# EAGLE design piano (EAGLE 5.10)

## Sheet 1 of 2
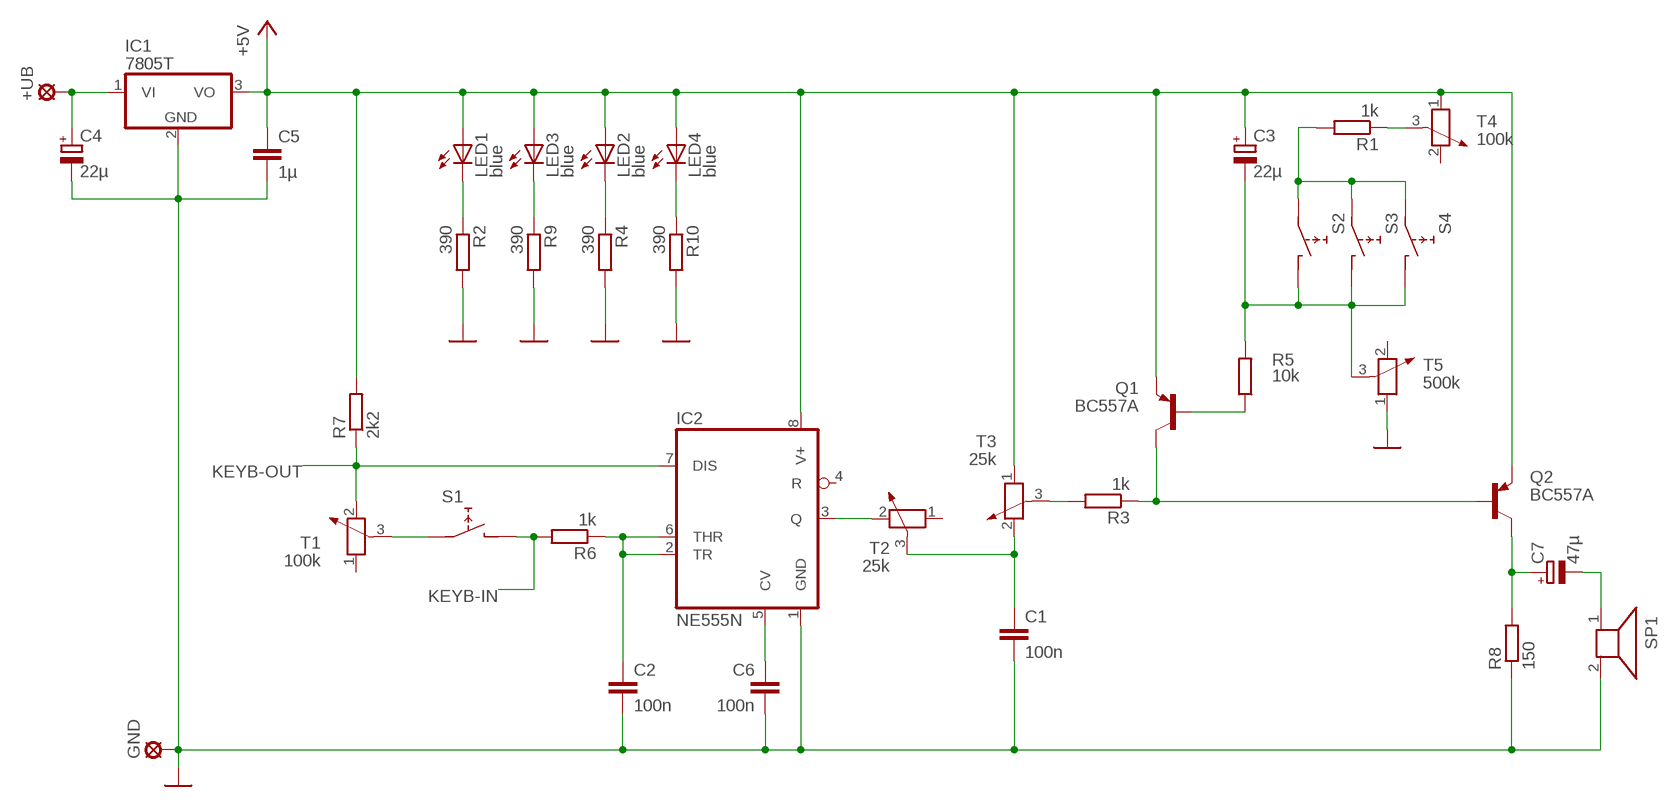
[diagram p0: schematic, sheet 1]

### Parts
+UB  LSP10  [LSP10]
C1  100n  C-EU075-063X106  [C075-063X106]
C2  100n  C-EU075-063X106  [C075-063X106]
C3  22µ  CPOL-EUB45181D  [B45181D]
C4  22µ  CPOL-EUB45181D  [B45181D]
C5  1µ  C-EU075-063X106  [C075-063X106]
C6  100n  C-EU075-063X106  [C075-063X106]
C7  47µ  CPOL-EUB45181D  [B45181D]
GND  LSP10  [LSP10]
IC1  7805T  [TO220H]
IC2  NE555N  [DIL08]
LED1  blue  LED5MM  [LED5MM]
LED2  blue  LED5MM  [LED5MM]
LED3  blue  LED5MM  [LED5MM]
LED4  blue  LED5MM  [LED5MM]
Q1  BC557A  [TO92-EBC]
Q2  BC557A  [TO92-EBC]
R1  1k  R-EU_0613/15  [P0613/15]
R2  390  R-EU_0613/15  [P0613/15]
R3  1k  R-EU_0613/15  [P0613/15]
R4  390  R-EU_0613/15  [P0613/15]
R5  10k  R-EU_0613/15  [P0613/15]
R6  1k  R-EU_0613/15  [P0613/15]
R7  2k2  R-EU_0613/15  [P0613/15]
R8  150  R-EU_0411/15  [0411/15]
R9  390  R-EU_0613/15  [P0613/15]
R10  390  R-EU_0613/15  [P0613/15]
S1  SWITCH  [RDT1034]
S2  SWITCH  [RDT1034]
S3  SWITCH  [RDT1034]
S4  SWITCH  [RDT1034]
SP1  AL23P  [AL23P]
T1  100k  POTENTIOMETER_PT-10S  [PT-10S]
T2  25k  POTENTIOMETER_PT-10S  [PT-10S]
T3  25k  POTENTIOMETER_PT-10S  [PT-10S]
T4  100k  POTENTIOMETER_PT-10S  [PT-10S]
T5  500k  POTENTIOMETER_PT-10S  [PT-10S]

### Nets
+5V: C3.+ C5.1 IC1.3(VO) IC2.8(V+) LED1.A LED2.A LED3.A LED4.A Q1.E Q2.E R7.2 T3.1 T4.1
GND: C1.2 C2.2 C4.- C5.2 C6.2 GND.MP IC1.2(GND) IC2.1(GND) R2.2 R4.2 R8.1 R9.2 R10.2 SP1.2 T5.1
KEYB-IN: R6.2 S1.B ; also sheet 2
KEYB-OUT: IC2.7(DIS) R7.1 T1.2 ; also sheet 2
N$1: IC2.3(Q) T2.2
N$2: C2.1 IC2.2(TR) IC2.6(THR) R6.1
N$3: C1.1 T2.3 T3.2
N$4: Q1.C Q2.B R3.1
N$5: C7.+ Q2.C R8.2
N$6: C6.1 IC2.5(CV)
N$7: LED1.K(C) R2.1
N$8: C7.- SP1.1
N$9: +UB.MP C4.+ IC1.1(VI)
N$10: R1.2 S2.A S3.A S4.A
N$11: S1.A T1.3
N$12: C3.- R5.2 S2.B S3.B S4.B T5.3
N$13: Q1.B R5.1
N$14: R3.2 T3.3
N$15: LED3.K(C) R9.1
N$16: LED2.K(C) R4.1
N$89: LED4.K(C) R10.1
N$90: R1.1 T4.3
Unconnected: IC2.4(R) T1.1 T2.1 T4.2 T5.2

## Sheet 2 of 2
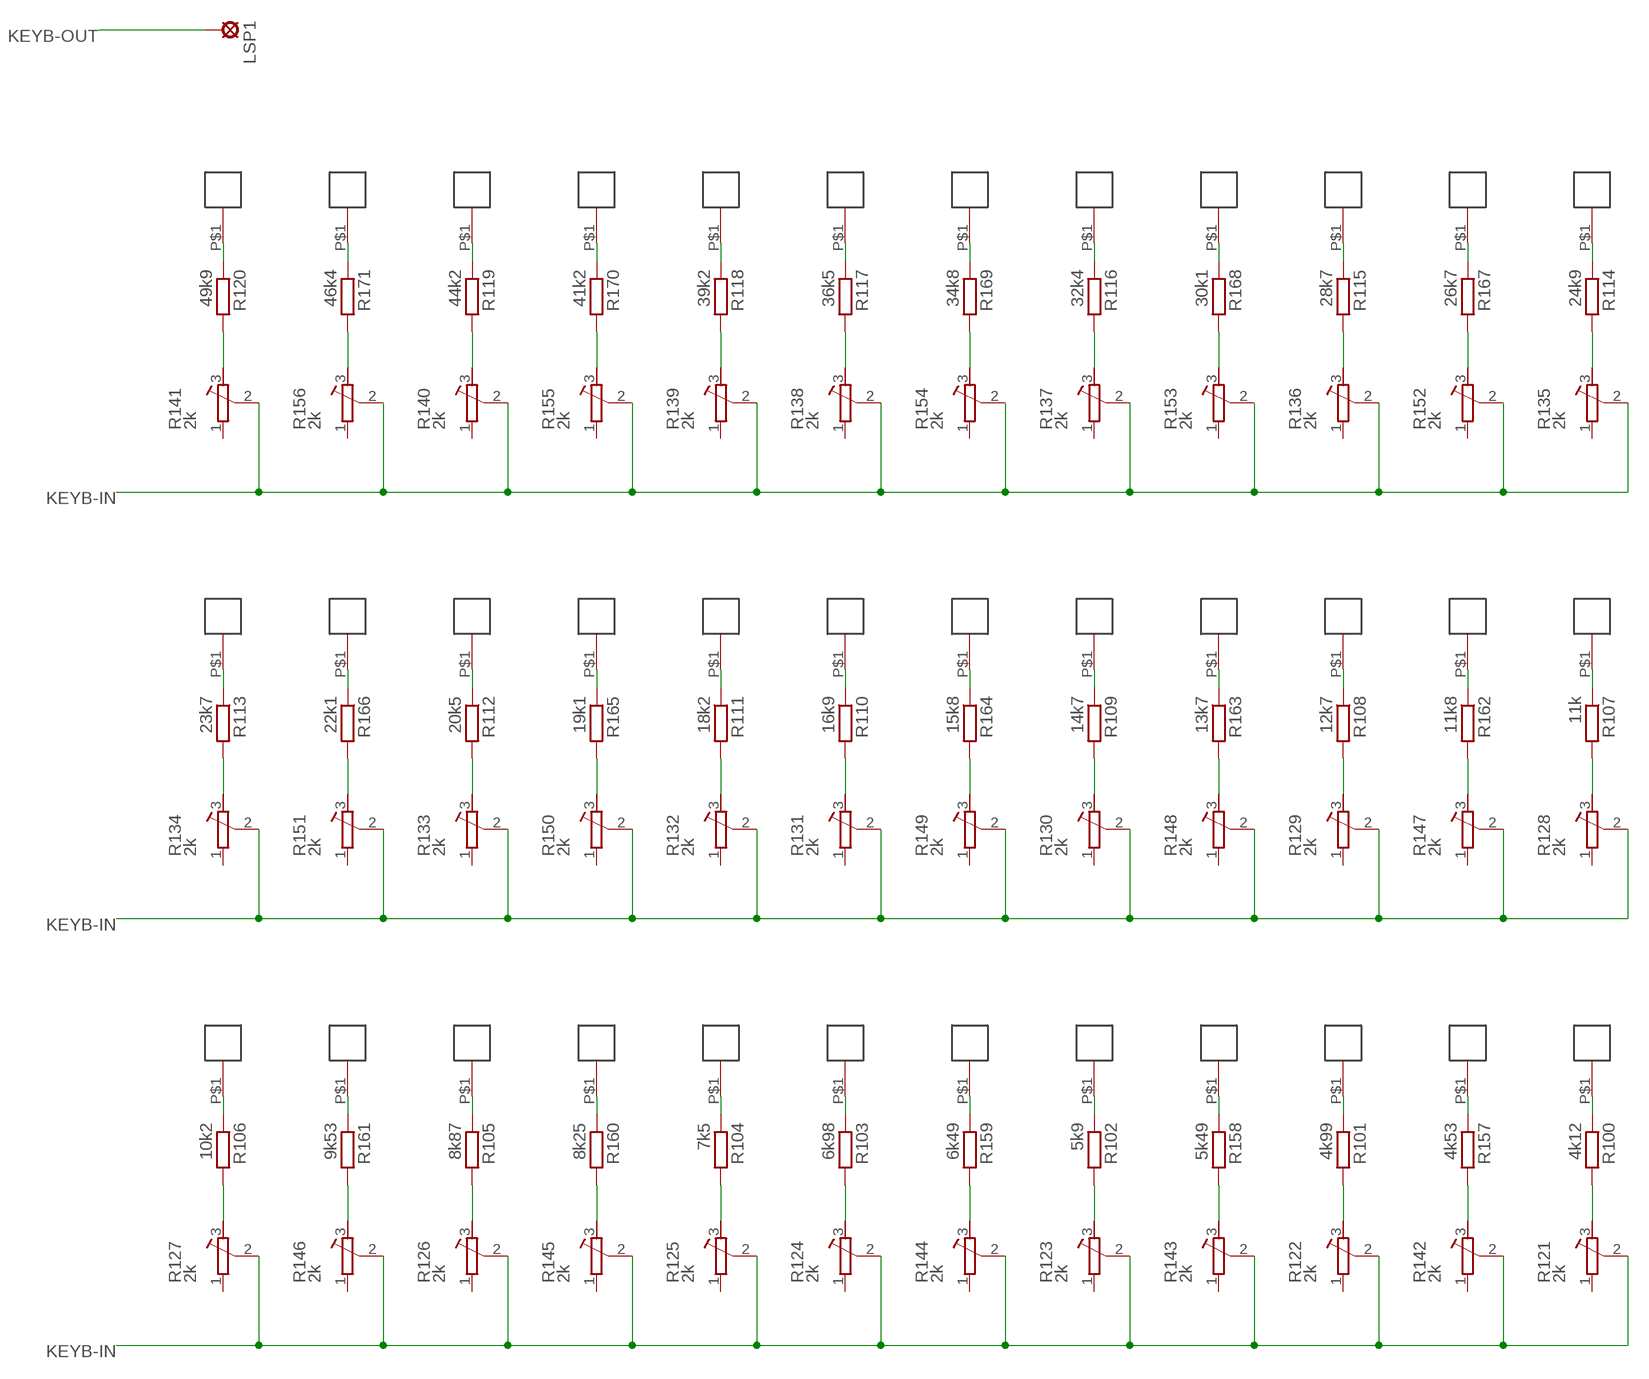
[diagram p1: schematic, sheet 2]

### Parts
KEY1  KEY  [KEY]
KEY2  KEY  [KEY]
KEY3  KEY  [KEY]
KEY4  KEY  [KEY]
KEY5  KEY  [KEY]
KEY6  KEY  [KEY]
KEY7  KEY  [KEY]
KEY8  KEY  [KEY]
KEY9  KEY  [KEY]
KEY10  KEY  [KEY]
KEY11  KEY  [KEY]
KEY12  KEY  [KEY]
KEY13  KEY  [KEY]
KEY14  KEY  [KEY]
KEY15  KEY  [KEY]
KEY16  KEY  [KEY]
KEY17  KEY  [KEY]
KEY18  KEY  [KEY]
KEY19  KEY  [KEY]
KEY20  KEY  [KEY]
KEY21  KEY  [KEY]
KEY22  KEY  [KEY]
KEY23  KEY  [KEY]
KEY24  KEY  [KEY]
KEY25  KEY  [KEY]
KEY26  KEY  [KEY]
KEY27  KEY  [KEY]
KEY28  KEY  [KEY]
KEY29  KEY  [KEY]
KEY30  KEY  [KEY]
KEY31  KEY  [KEY]
KEY32  KEY  [KEY]
KEY33  KEY  [KEY]
KEY34  KEY  [KEY]
KEY35  KEY  [KEY]
KEY36  KEY  [KEY]
LSP1  LSP10  [LSP10]
R100  4k12  R-EU_R0805  [R0805]
R101  4k99  R-EU_R0805  [R0805]
R102  5k9  R-EU_R0805  [R0805]
R103  6k98  R-EU_R0805  [R0805]
R104  7k5  R-EU_R0805  [R0805]
R105  8k87  R-EU_R0805  [R0805]
R106  10k2  R-EU_R0805  [R0805]
R107  11k  R-EU_R0805  [R0805]
R108  12k7  R-EU_R0805  [R0805]
R109  14k7  R-EU_R0805  [R0805]
R110  16k9  R-EU_R0805  [R0805]
R111  18k2  R-EU_R0805  [R0805]
R112  20k5  R-EU_R0805  [R0805]
R113  23k7  R-EU_R0805  [R0805]
R114  24k9  R-EU_R0805  [R0805]
R115  28k7  R-EU_R0805  [R0805]
R116  32k4  R-EU_R0805  [R0805]
R117  36k5  R-EU_R0805  [R0805]
R118  39k2  R-EU_R0805  [R0805]
R119  44k2  R-EU_R0805  [R0805]
R120  49k9  R-EU_R0805  [R0805]
R121  2k  R-TRIMM4G/J  [TRIMMER]
R122  2k  R-TRIMM4G/J  [TRIMMER]
R123  2k  R-TRIMM4G/J  [TRIMMER]
R124  2k  R-TRIMM4G/J  [TRIMMER]
R125  2k  R-TRIMM4G/J  [TRIMMER]
R126  2k  R-TRIMM4G/J  [TRIMMER]
R127  2k  R-TRIMM4G/J  [TRIMMER]
R128  2k  R-TRIMM4G/J  [TRIMMER]
R129  2k  R-TRIMM4G/J  [TRIMMER]
R130  2k  R-TRIMM4G/J  [TRIMMER]
R131  2k  R-TRIMM4G/J  [TRIMMER]
R132  2k  R-TRIMM4G/J  [TRIMMER]
R133  2k  R-TRIMM4G/J  [TRIMMER]
R134  2k  R-TRIMM4G/J  [TRIMMER]
R135  2k  R-TRIMM4G/J  [TRIMMER]
R136  2k  R-TRIMM4G/J  [TRIMMER]
R137  2k  R-TRIMM4G/J  [TRIMMER]
R138  2k  R-TRIMM4G/J  [TRIMMER]
R139  2k  R-TRIMM4G/J  [TRIMMER]
R140  2k  R-TRIMM4G/J  [TRIMMER]
R141  2k  R-TRIMM4G/J  [TRIMMER]
R142  2k  R-TRIMM4G/J  [TRIMMER]
R143  2k  R-TRIMM4G/J  [TRIMMER]
R144  2k  R-TRIMM4G/J  [TRIMMER]
R145  2k  R-TRIMM4G/J  [TRIMMER]
R146  2k  R-TRIMM4G/J  [TRIMMER]
R147  2k  R-TRIMM4G/J  [TRIMMER]
R148  2k  R-TRIMM4G/J  [TRIMMER]
R149  2k  R-TRIMM4G/J  [TRIMMER]
R150  2k  R-TRIMM4G/J  [TRIMMER]
R151  2k  R-TRIMM4G/J  [TRIMMER]
R152  2k  R-TRIMM4G/J  [TRIMMER]
R153  2k  R-TRIMM4G/J  [TRIMMER]
R154  2k  R-TRIMM4G/J  [TRIMMER]
R155  2k  R-TRIMM4G/J  [TRIMMER]
R156  2k  R-TRIMM4G/J  [TRIMMER]
R157  4k53  R-EU_R0805  [R0805]
R158  5k49  R-EU_R0805  [R0805]
R159  6k49  R-EU_R0805  [R0805]
R160  8k25  R-EU_R0805  [R0805]
R161  9k53  R-EU_R0805  [R0805]
R162  11k8  R-EU_R0805  [R0805]
R163  13k7  R-EU_R0805  [R0805]
R164  15k8  R-EU_R0805  [R0805]
R165  19k1  R-EU_R0805  [R0805]
R166  22k1  R-EU_R0805  [R0805]
R167  26k7  R-EU_R0805  [R0805]
R168  30k1  R-EU_R0805  [R0805]
R169  34k8  R-EU_R0805  [R0805]
R170  41k2  R-EU_R0805  [R0805]
R171  46k4  R-EU_R0805  [R0805]

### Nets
KEYB-IN: R121.2(S) R122.2(S) R123.2(S) R124.2(S) R125.2(S) R126.2(S) R127.2(S) R128.2(S) R129.2(S) R130.2(S) R131.2(S) R132.2(S) R133.2(S) R134.2(S) R135.2(S) R136.2(S) R137.2(S) R138.2(S) R139.2(S) R140.2(S) R141.2(S) R142.2(S) R143.2(S) R144.2(S) R145.2(S) R146.2(S) R147.2(S) R148.2(S) R149.2(S) R150.2(S) R151.2(S) R152.2(S) R153.2(S) R154.2(S) R155.2(S) R156.2(S) ; also sheet 1
KEYB-OUT: LSP1.MP ; also sheet 1
N$17: KEY16.P$1(A) R120.1
N$18: R120.2 R141.3(A)
N$19: KEY1.P$1(A) R171.1
N$20: R156.3(A) R171.2
N$21: KEY17.P$1(A) R119.1
N$22: R119.2 R140.3(A)
N$23: KEY2.P$1(A) R170.1
N$24: R155.3(A) R170.2
N$25: KEY18.P$1(A) R118.1
N$26: R118.2 R139.3(A)
N$27: KEY19.P$1(A) R117.1
N$28: R117.2 R138.3(A)
N$29: KEY3.P$1(A) R169.1
N$30: R154.3(A) R169.2
N$31: KEY20.P$1(A) R116.1
N$32: R116.2 R137.3(A)
N$33: KEY4.P$1(A) R168.1
N$34: R153.3(A) R168.2
N$35: KEY21.P$1(A) R115.1
N$36: R115.2 R136.3(A)
N$37: KEY5.P$1(A) R167.1
N$38: R152.3(A) R167.2
N$39: KEY22.P$1(A) R114.1
N$40: R114.2 R135.3(A)
N$41: KEY23.P$1(A) R113.1
N$42: R113.2 R134.3(A)
N$43: KEY6.P$1(A) R166.1
N$44: R151.3(A) R166.2
N$45: KEY24.P$1(A) R112.1
N$46: R112.2 R133.3(A)
N$47: KEY7.P$1(A) R165.1
N$48: R150.3(A) R165.2
N$49: KEY25.P$1(A) R111.1
N$50: R111.2 R132.3(A)
N$51: KEY26.P$1(A) R110.1
N$52: R110.2 R131.3(A)
N$53: KEY8.P$1(A) R164.1
N$54: R149.3(A) R164.2
N$55: KEY27.P$1(A) R109.1
N$56: R109.2 R130.3(A)
N$57: KEY9.P$1(A) R163.1
N$58: R148.3(A) R163.2
N$59: KEY28.P$1(A) R108.1
N$60: R108.2 R129.3(A)
N$61: KEY10.P$1(A) R162.1
N$62: R147.3(A) R162.2
N$63: KEY29.P$1(A) R107.1
N$64: R107.2 R128.3(A)
N$65: KEY30.P$1(A) R106.1
N$66: R106.2 R127.3(A)
N$67: KEY11.P$1(A) R161.1
N$68: R146.3(A) R161.2
N$69: KEY31.P$1(A) R105.1
N$70: R105.2 R126.3(A)
N$71: KEY12.P$1(A) R160.1
N$72: R145.3(A) R160.2
N$73: KEY32.P$1(A) R104.1
N$74: R104.2 R125.3(A)
N$75: KEY33.P$1(A) R103.1
N$76: R103.2 R124.3(A)
N$77: KEY13.P$1(A) R159.1
N$78: R144.3(A) R159.2
N$79: KEY34.P$1(A) R102.1
N$80: R102.2 R123.3(A)
N$81: KEY14.P$1(A) R158.1
N$82: R143.3(A) R158.2
N$83: KEY35.P$1(A) R101.1
N$84: R101.2 R122.3(A)
N$85: KEY15.P$1(A) R157.1
N$86: R142.3(A) R157.2
N$87: KEY36.P$1(A) R100.1
N$88: R100.2 R121.3(A)
Unconnected: R121.1(E) R122.1(E) R123.1(E) R124.1(E) R125.1(E) R126.1(E) R127.1(E) R128.1(E) R129.1(E) R130.1(E) R131.1(E) R132.1(E) R133.1(E) R134.1(E) R135.1(E) R136.1(E) R137.1(E) R138.1(E) R139.1(E) R140.1(E) R141.1(E) R142.1(E) R143.1(E) R144.1(E) R145.1(E) R146.1(E) R147.1(E) R148.1(E) R149.1(E) R150.1(E) R151.1(E) R152.1(E) R153.1(E) R154.1(E) R155.1(E) R156.1(E)

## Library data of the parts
+UB GND LSP1 = solpad:LSP10: SOLDER PAD
C1 C2 C5 C6 = rcl:C-EU: CAPACITOR, European symbol
C3 C4 C7 = rcl:CPOL-EU: POLARIZED CAPACITOR, European symbol
IC1 = linear:78*: Positive VOLTAGE REGULATOR Source: http://cache.national.com/ds/LM/LM78L05.pdf http://www.fairchildsemi.com/ds/LM/LM7805.pdf
IC2 = 555:*555: TIMER
KEY1-KEY36 = 555:KEY
LED1-LED4 = led:LED: LED
Q1 Q2 = transistor-pnp:BC557*: PNP Transistror
R1-R10 R100-R120 R157-R171 = rcl:R-EU_: RESISTOR, European symbol
R121-R156 = 555:R-TRIMM: Trimm resistor
S1-S4 = 555:SWITCH: PUSH SWITCH
SP1 = buzzer:AL23P: SPEAKER
T1-T5 = rcl:POTENTIOMETER_: Potentiometer

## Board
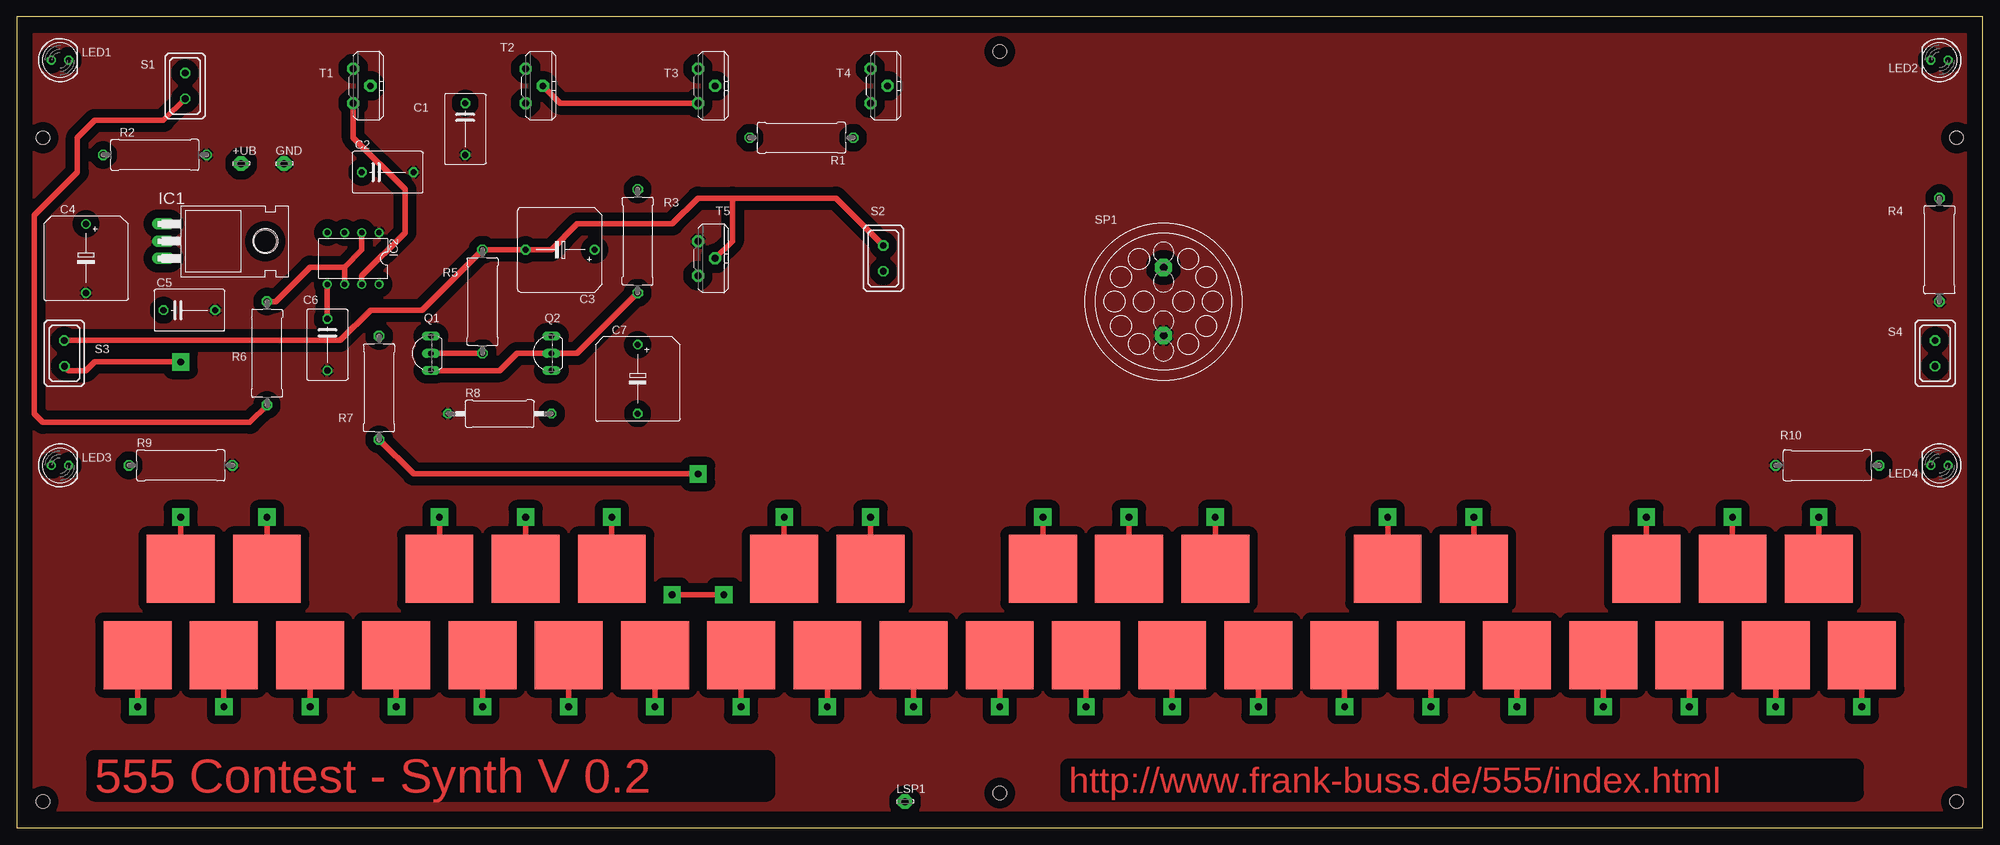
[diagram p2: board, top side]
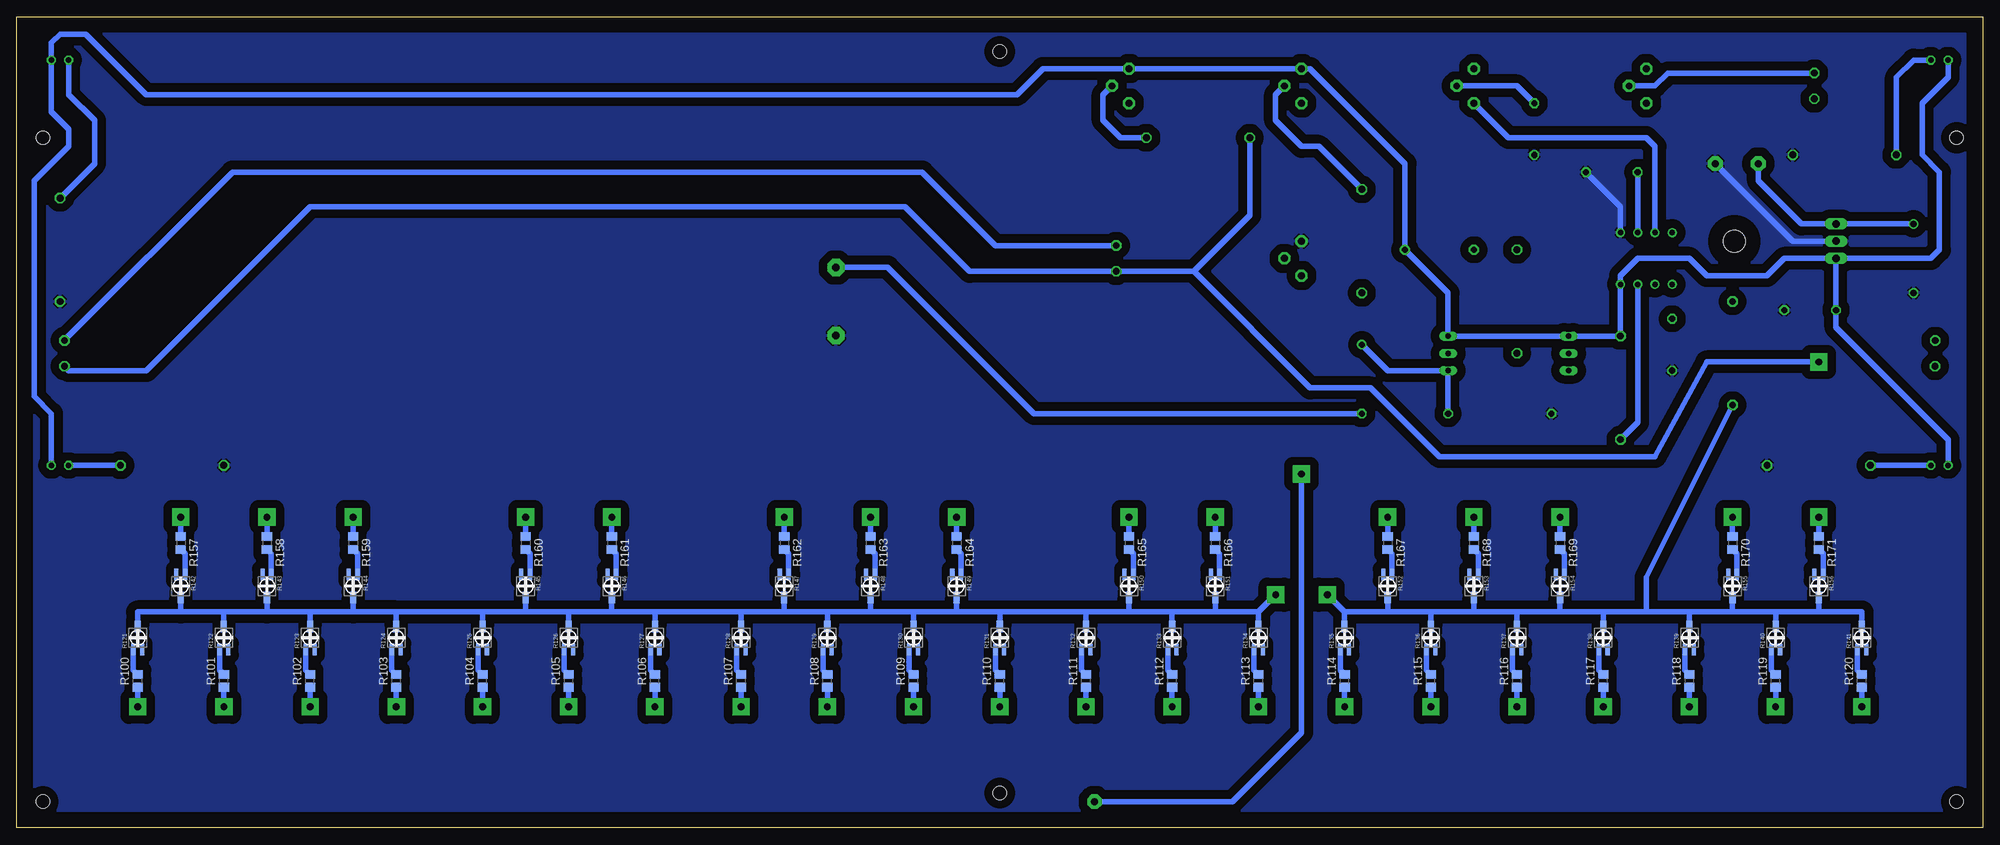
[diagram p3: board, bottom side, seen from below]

Size 289.56 x 119.38 mm. Coordinates in mm from the lower left corner, seen from the top.
Outline: 0,0 289.56,0 289.56,119.38 0,119.38 0,0
Copper layers (1*16): Top 0.035mm / dielectric 1.5mm / Bottom 0.035mm
Design rules "default": minimum track width 10mil, minimum drill 24mil, track to track 8mil, track to pad 8mil, pad to pad 8mil, via to via 8mil, smd to smd 8mil, copper to edge 40mil, drill to drill 8mil, minimum pad ring 10mil, minimum via ring 8mil, stop-mask expansion 4mil, vias tented up to drill 0mil, thermal gap 10mil
Holes 2 mm at 3.81,101.6 285.75,101.6 144.78,114.3 144.78,5.08 285.75,3.81 3.81,3.81

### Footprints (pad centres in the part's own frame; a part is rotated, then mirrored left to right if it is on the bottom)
LSP10 = drill 1.016 pad 2.159 octagon: MP 0,0
C075-063X106 = drill 0.914 octagon: 1 -3.81,0; 2 3.81,0
B45181D = drill 0.914 round: + -5.08,0 | drill 0.914 octagon: - 5.08,0
TO220H = drill 1.118 long: 1 -2.54,-10.16; 2 0,-10.16; 3 2.54,-10.16 | hole 3.302: 0,4.826
DIL08 = drill 0.813 pad 1.27 round: 1 -3.81,-3.81; 2 -1.27,-3.81; 3 1.27,-3.81; 4 3.81,-3.81; 5 3.81,3.81; 6 1.27,3.81; 7 -1.27,3.81; 8 -3.81,3.81
KEY = smd 10 x 10: P$1 0,0
LED5MM = drill 0.813 octagon: A -1.27,0; K 1.27,0
TO92-EBC = drill 0.813 long: B 0,-1.27; C -2.54,-1.27; E 2.54,-1.27
P0613/15 = drill 1.016 octagon: 1 -7.62,0; 2 7.62,0
0411/15 = drill 0.914 octagon: 1 -7.62,0; 2 7.62,0
R0805 = smd 1.3 x 1.5: 1 -0.95,0; 2 0.95,0
TRIMMER = smd 0.6 x 1.7: 1 0.65,-1.7; 3 -0.65,-1.7 | smd 0.9 x 1.7: 2 0,1.7
RDT1034 = drill 1 octagon: A 1.905,0.635; B -1.89,0.63
AL23P = drill 1.118 pad 2.54 octagon: 1 -5.004,0; 2 5.004,0
PT-10S = drill 1.016 pad 1.778 octagon: 1 -2.54,-1.27; 2 2.54,-1.27; 3 0,1.27

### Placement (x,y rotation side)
+UB  33.02,97.79 0 top
C1  66.04,102.87 270 top
C2  54.61,96.52 0 top
C3  80.01,85.09 180 top
C4  10.16,83.82 270 top
C5  25.4,76.2 0 top
C6  45.72,71.12 270 top
C7  91.44,66.04 270 top
GND  39.37,97.79 0 top
IC1  31.75,86.36 270 top
IC2  49.53,83.82 180 top
KEY1  24.13,38.1 0 top
KEY2  36.83,38.1 0 top
KEY3  62.23,38.1 0 top
KEY4  74.93,38.1 0 top
KEY5  87.63,38.1 0 top
KEY6  113.03,38.1 0 top
KEY7  125.73,38.1 0 top
KEY8  151.13,38.1 0 top
KEY9  163.83,38.1 0 top
KEY10  176.53,38.1 0 top
KEY11  201.93,38.1 0 top
KEY12  214.63,38.1 0 top
KEY13  240.03,38.1 0 top
KEY14  252.73,38.1 0 top
KEY15  265.43,38.1 0 top
KEY16  17.78,25.4 0 top
KEY17  30.48,25.4 0 top
KEY18  43.18,25.4 0 top
KEY19  55.88,25.4 0 top
KEY20  68.58,25.4 0 top
KEY21  81.28,25.4 0 top
KEY22  93.98,25.4 0 top
KEY23  106.68,25.4 0 top
KEY24  119.38,25.4 0 top
KEY25  132.08,25.4 0 top
KEY26  144.78,25.4 0 top
KEY27  157.48,25.4 0 top
KEY28  170.18,25.4 0 top
KEY29  182.88,25.4 0 top
KEY30  195.58,25.4 0 top
KEY31  208.28,25.4 0 top
KEY32  220.98,25.4 0 top
KEY33  233.68,25.4 0 top
KEY34  246.38,25.4 0 top
KEY35  259.08,25.4 0 top
KEY36  271.78,25.4 0 top
LED1  6.35,113.03 0 top
LED2  283.21,113.03 180 top
LED3  6.35,53.34 0 top
LED4  283.21,53.34 180 top
LSP1  130.81,3.81 0 top
Q1  59.69,69.85 90 top
Q2  77.47,69.85 90 top
R1  115.57,101.6 180 top
R2  20.32,99.06 0 top
R3  91.44,86.36 90 top
R4  283.21,85.09 270 top
R5  68.58,77.47 90 top
R6  36.83,69.85 270 top
R7  53.34,64.77 90 top
R8  71.12,60.96 0 top
R9  24.13,53.34 0 top
R10  266.7,53.34 180 top
R100  271.78,21.59 90 bottom
R101  259.08,21.59 90 bottom
R102  246.38,21.59 90 bottom
R103  233.68,21.59 90 bottom
R104  220.98,21.59 90 bottom
R105  208.28,21.59 90 bottom
R106  195.58,21.59 90 bottom
R107  182.88,21.59 90 bottom
R108  170.18,21.59 90 bottom
R109  157.48,21.59 90 bottom
R110  144.78,21.59 90 bottom
R111  132.08,21.59 90 bottom
R112  119.38,21.59 90 bottom
R113  106.68,21.59 90 bottom
R114  93.98,21.59 90 bottom
R115  81.28,21.59 90 bottom
R116  68.58,21.59 90 bottom
R117  55.88,21.59 90 bottom
R118  43.18,21.59 90 bottom
R119  30.48,21.59 90 bottom
R120  17.78,21.59 90 bottom
R121  271.78,27.94 0 bottom
R122  259.08,27.94 0 bottom
R123  246.38,27.94 0 bottom
R124  233.68,27.94 0 bottom
R125  220.98,27.94 0 bottom
R126  208.28,27.94 0 bottom
R127  195.58,27.94 0 bottom
R128  182.88,27.94 0 bottom
R129  170.18,27.94 0 bottom
R130  157.48,27.94 0 bottom
R131  144.78,27.94 0 bottom
R132  132.08,27.94 0 bottom
R133  119.38,27.94 0 bottom
R134  106.68,27.94 0 bottom
R135  93.98,27.94 0 bottom
R136  81.28,27.94 0 bottom
R137  68.58,27.94 0 bottom
R138  55.88,27.94 0 bottom
R139  43.18,27.94 0 bottom
R140  30.48,27.94 0 bottom
R141  17.78,27.94 0 bottom
R142  265.43,35.56 180 bottom
R143  252.73,35.56 180 bottom
R144  240.03,35.56 180 bottom
R145  214.63,35.56 180 bottom
R146  201.93,35.56 180 bottom
R147  176.53,35.56 180 bottom
R148  163.83,35.56 180 bottom
R149  151.13,35.56 180 bottom
R150  125.73,35.56 180 bottom
R151  113.03,35.56 180 bottom
R152  87.63,35.56 180 bottom
R153  74.93,35.56 180 bottom
R154  62.23,35.56 180 bottom
R155  36.83,35.56 180 bottom
R156  24.13,35.56 180 bottom
R157  265.43,41.91 270 bottom
R158  252.73,41.91 270 bottom
R159  240.03,41.91 270 bottom
R160  214.63,41.91 270 bottom
R161  201.93,41.91 270 bottom
R162  176.53,41.91 270 bottom
R163  163.83,41.91 270 bottom
R164  151.13,41.91 270 bottom
R165  125.73,41.91 270 bottom
R166  113.03,41.91 270 bottom
R167  87.63,41.91 270 bottom
R168  74.93,41.91 270 bottom
R169  62.23,41.91 270 bottom
R170  36.83,41.91 270 bottom
R171  24.13,41.91 270 bottom
S1  25.4,109.22 90 top
S2  127,83.82 270 top
S3  6.35,69.85 270 top
S4  281.94,69.85 270 top
SP1  168.91,77.47 270 top
T1  50.8,109.22 270 top
T2  76.2,109.22 270 top
T3  101.6,109.22 270 top
T4  127,109.22 270 top
T5  101.6,83.82 270 top

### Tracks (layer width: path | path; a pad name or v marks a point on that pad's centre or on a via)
+5V
  Bottom 0.813: IC1.3 C5.1 21.59,73.66 5.08,57.15 LED3.A | IC1.3 29.21,83.82 31.75,81.28 40.64,81.28 43.18,83.82 50.8,83.82 53.34,81.28 IC2.8 R7.2 Q1.E Q2.E 78.74,78.74 C3.+ 85.09,97.79 99.06,111.76 T3.1 T4.1 138.43,111.76 142.24,107.95 270.51,107.95 279.4,116.84 283.21,116.84 284.48,115.57 LED2.A 284.48,105.41 281.94,102.87 281.94,100.33 287.02,95.25 287.02,63.5 284.48,60.96 LED4.A | IC1.3 7.62,83.82 6.35,85.09 6.35,96.52 8.89,99.06 8.89,106.68 5.08,110.49 LED1.A
GND
  Bottom 0.813: IC1.2 27.94,86.36 GND.MP | IC2.1 53.34,91.44 C2.2
  pour Bottom (isolate 1.27): 287.02,116.84 287.02,2.54 2.54,2.54 2.54,116.84
  pour Top (isolate 1.27): 2.54,116.84 287.02,116.84 287.02,2.54 2.54,2.54
KEYB-IN  (via drill 1 pad 2.54)
  Top 0.813: S1.B 21.58,104.14 11.43,104.14 8.89,101.6 8.89,96.52 2.54,90.17 2.54,60.96 3.81,59.69 34.29,59.69 R6.2 | v104.14,34.29 v96.52,34.29
  Bottom 0.813: R6.2 49.53,36.83 49.53,31.75 | 49.53,31.75 43.18,31.75 | 43.18,31.75 R139.2 | 43.18,31.75 36.83,31.75 | 36.83,31.75 R155.2 | 36.83,31.75 30.48,31.75 | 30.48,31.75 R140.2 | 30.48,31.75 24.13,31.75 | 24.13,31.75 R156.2 | 24.13,31.75 17.78,31.75 R141.2 | 55.88,31.75 49.53,31.75 | 55.88,31.75 R138.2 | 62.23,31.75 55.88,31.75 | 62.23,31.75 R154.2 | 68.58,31.75 62.23,31.75 | 68.58,31.75 R137.2 | 74.93,31.75 68.58,31.75 | 74.93,31.75 R153.2 | 81.28,31.75 74.93,31.75 | 81.28,31.75 R136.2 | 87.63,31.75 81.28,31.75 | 87.63,31.75 R152.2 | 93.98,31.75 87.63,31.75 | 93.98,31.75 R135.2 | v96.52,34.29 93.98,31.75 | 106.68,31.75 v104.14,34.29 | 106.68,31.75 R134.2 | 113.03,31.75 106.68,31.75 | 113.03,31.75 R151.2 | 119.38,31.75 113.03,31.75 | 119.38,31.75 R133.2 | 125.73,31.75 119.38,31.75 | 125.73,31.75 R150.2 | 132.08,31.75 125.73,31.75 | 132.08,31.75 R132.2 | 144.78,31.75 132.08,31.75 | 144.78,31.75 R131.2 | 151.13,31.75 144.78,31.75 | 151.13,31.75 R149.2 | 157.48,31.75 151.13,31.75 | 157.48,31.75 R130.2 | 163.83,31.75 157.48,31.75 | 163.83,31.75 R148.2 | 170.18,31.75 163.83,31.75 | 170.18,31.75 R129.2 | 176.53,31.75 170.18,31.75 | 176.53,31.75 R147.2 | 182.88,31.75 176.53,31.75 | 182.88,31.75 R128.2 | 195.58,31.75 182.88,31.75 | 195.58,31.75 R127.2 | 201.93,31.75 195.58,31.75 | 201.93,31.75 R146.2 | 208.28,31.75 201.93,31.75 | 208.28,31.75 R126.2 | 214.63,31.75 208.28,31.75 | 214.63,31.75 R145.2 | 220.98,31.75 214.63,31.75 | 220.98,31.75 R125.2 | 233.68,31.75 220.98,31.75 | R124.2 233.68,31.75 | 233.68,31.75 240.03,31.75 | 240.03,31.75 R144.2 | 240.03,31.75 246.38,31.75 | 246.38,31.75 R123.2 | 246.38,31.75 252.73,31.75 | 252.73,31.75 R143.2 | 252.73,31.75 259.08,31.75 | 259.08,31.75 R122.2
  Bottom 0.813: 259.08,31.75 265.43,31.75 | 265.43,31.75 R142.2 | 265.43,31.75 271.78,31.75 R121.2
KEYB-OUT  (via drill 1 pad 2.54)
  Top 0.813: R7.1 58.42,52.07 v100.33,52.07 | IC2.7 50.8,81.28 57.15,87.63 57.15,93.98 49.53,101.6 T1.2
  Bottom 0.813: R7.1 50.8,59.69 IC2.7 | v100.33,52.07 100.33,13.97 110.49,3.81 LSP1.MP
N$1
  Bottom 0.813: IC2.3 48.26,100.33 49.53,101.6 69.85,101.6 T2.2
N$2
  Top 0.813: IC2.2 50.8,85.09 48.26,82.55 | 48.26,82.55 IC2.6 | 48.26,82.55 43.18,82.55 38.1,77.47 R6.1
  Bottom 0.813: IC2.2 C2.1
N$3
  Top 0.813: T2.3 80.01,106.68 T3.2
  Bottom 0.813: C1.1 68.58,109.22 T2.3
N$4
  Top 0.813: R3.1 82.55,69.85 Q2.B 73.66,69.85 71.12,67.31 Q1.C
N$5
  Bottom 0.813: R8.2 Q2.C 87.63,67.31 C7.+
N$6
  Top 0.813: C6.1 IC2.5
N$7
  Bottom 0.813: R2.1 12.7,110.49 10.16,113.03 LED1.K
N$8
  Bottom 0.813: C7.- 139.7,60.96 161.29,82.55 168.83,82.55 SP1.1
N$9
  Bottom 0.813: +UB.MP 33.02,95.25 26.67,88.9 IC1.1 C4.+
N$10  (via drill 1 pad 2.54)
  Top 0.813: v24.13,68.58 11.43,68.58 10.16,67.31 7.62,67.31 S3.A
  Bottom 0.813: S4.A 281.94,67.31 270.51,67.31 246.38,91.44 158.75,91.44 149.22,81.92 S2.A 116.2,81.92 | 116.2,81.92 99.06,64.77 90.17,64.77 80.01,54.61 48.26,54.61 40.64,68.58 v24.13,68.58 | R1.2 107.95,90.17 116.2,81.92
N$11
  Bottom 0.813: S1.A 46.35,111.12 48.26,109.22 T1.3
N$12
  Top 0.813: S3.B 47.61,71.74 52.07,76.2 59.69,76.2 R5.2 C3.- 78.74,85.09 82.55,88.9 96.52,88.9 100.33,92.71 105.41,92.71 | 105.41,92.71 120.63,92.71 S2.B | T5.3 105.41,86.36 105.41,92.71
  Bottom 0.813: S2.B 145.4,85.71 156.21,96.52 257.79,96.52 S4.B
N$13
  Top 0.813: Q1.B R5.1
N$14
  Bottom 0.813: R3.2 97.79,100.33 100.33,100.33 104.14,104.14 104.14,107.95 T3.3
N$15
  Bottom 0.813: LED3.K R9.1
N$16
  Bottom 0.813: LED2.K 281.94,107.95 278.13,104.14 278.13,97.79 R4.1
N$17  (via drill 1 pad 2.54)
  Top 0.813: v17.78,17.78 KEY16.P$1
  Bottom 0.813: v17.78,17.78 R120.1
N$18
  Bottom 0.813: R120.2 18.43,23.19 R141.3
N$19  (via drill 1 pad 2.54)
  Top 0.813: KEY1.P$1 v24.13,45.72
  Bottom 0.813: v24.13,45.72 R171.1
N$20
  Bottom 0.813: R171.2 23.48,40.31 R156.3
N$21  (via drill 1 pad 2.54)
  Top 0.813: v30.48,17.78 KEY17.P$1
  Bottom 0.813: v30.48,17.78 R119.1
N$22
  Bottom 0.813: R119.2 31.13,23.19 R140.3
N$23  (via drill 1 pad 2.54)
  Top 0.813: KEY2.P$1 v36.83,45.72
  Bottom 0.813: v36.83,45.72 R170.1
N$24
  Bottom 0.813: R170.2 36.18,40.31 R155.3
N$25  (via drill 1 pad 2.54)
  Top 0.813: v43.18,17.78 KEY18.P$1
  Bottom 0.813: v43.18,17.78 R118.1
N$26
  Bottom 0.813: R118.2 43.83,23.19 R139.3
N$27  (via drill 1 pad 2.54)
  Top 0.813: v55.88,17.78 KEY19.P$1
  Bottom 0.813: v55.88,17.78 R117.1
N$28
  Bottom 0.813: R117.2 56.53,23.19 R138.3
N$29  (via drill 1 pad 2.54)
  Top 0.813: KEY3.P$1 v62.23,45.72
  Bottom 0.813: v62.23,45.72 R169.1
N$30
  Bottom 0.813: R169.2 61.58,40.31 R154.3
N$31  (via drill 1 pad 2.54)
  Top 0.813: v68.58,17.78 KEY20.P$1
  Bottom 0.813: v68.58,17.78 R116.1
N$32
  Bottom 0.813: R116.2 69.23,23.19 R137.3
N$33  (via drill 1 pad 2.54)
  Top 0.813: KEY4.P$1 v74.93,45.72
  Bottom 0.813: v74.93,45.72 R168.1
N$34
  Bottom 0.813: R168.2 74.28,40.31 R153.3
N$35  (via drill 1 pad 2.54)
  Top 0.813: v81.28,17.78 KEY21.P$1
  Bottom 0.813: v81.28,17.78 R115.1
N$36
  Bottom 0.813: R115.2 81.93,23.19 R136.3
N$37  (via drill 1 pad 2.54)
  Top 0.813: KEY5.P$1 v87.63,45.72
  Bottom 0.813: v87.63,45.72 R167.1
N$38
  Bottom 0.813: R167.2 86.98,40.31 R152.3
N$39  (via drill 1 pad 2.54)
  Top 0.813: v93.98,17.78 KEY22.P$1
  Bottom 0.813: v93.98,17.78 R114.1
N$40
  Bottom 0.813: R114.2 94.63,23.19 R135.3
N$41  (via drill 1 pad 2.54)
  Top 0.813: v106.68,17.78 KEY23.P$1
  Bottom 0.813: v106.68,17.78 R113.1
N$42
  Bottom 0.813: R113.2 107.33,23.19 R134.3
N$43  (via drill 1 pad 2.54)
  Top 0.813: KEY6.P$1 v113.03,45.72
  Bottom 0.813: v113.03,45.72 R166.1
N$44
  Bottom 0.813: R166.2 112.38,40.31 R151.3
N$45  (via drill 1 pad 2.54)
  Top 0.813: v119.38,17.78 KEY24.P$1
  Bottom 0.813: v119.38,17.78 R112.1
N$46
  Bottom 0.813: R112.2 120.03,23.19 R133.3
N$47  (via drill 1 pad 2.54)
  Top 0.813: KEY7.P$1 v125.73,45.72
  Bottom 0.813: v125.73,45.72 R165.1
N$48
  Bottom 0.813: R165.2 125.08,40.31 R150.3
N$49  (via drill 1 pad 2.54)
  Top 0.813: v132.08,17.78 KEY25.P$1
  Bottom 0.813: v132.08,17.78 R111.1
N$50
  Bottom 0.813: R111.2 132.73,23.19 R132.3
N$51  (via drill 1 pad 2.54)
  Top 0.813: v144.78,17.78 KEY26.P$1
  Bottom 0.813: v144.78,17.78 R110.1
N$52
  Bottom 0.813: R110.2 145.43,23.19 R131.3
N$53  (via drill 1 pad 2.54)
  Top 0.813: KEY8.P$1 v151.13,45.72
  Bottom 0.813: v151.13,45.72 R164.1
N$54
  Bottom 0.813: R164.2 150.48,40.31 R149.3
N$55  (via drill 1 pad 2.54)
  Top 0.813: v157.48,17.78 KEY27.P$1
  Bottom 0.813: v157.48,17.78 R109.1
N$56
  Bottom 0.813: R109.2 158.13,23.19 R130.3
N$57  (via drill 1 pad 2.54)
  Top 0.813: KEY9.P$1 v163.83,45.72
  Bottom 0.813: v163.83,45.72 R163.1
N$58
  Bottom 0.813: R163.2 163.18,40.31 R148.3
N$59  (via drill 1 pad 2.54)
  Top 0.813: v170.18,17.78 KEY28.P$1
  Bottom 0.813: v170.18,17.78 R108.1
N$60
  Bottom 0.813: R108.2 170.83,23.19 R129.3
N$61  (via drill 1 pad 2.54)
  Top 0.813: KEY10.P$1 v176.53,45.72
  Bottom 0.813: v176.53,45.72 R162.1
N$62
  Bottom 0.813: R162.2 175.88,40.31 R147.3
N$63  (via drill 1 pad 2.54)
  Top 0.813: v182.88,17.78 KEY29.P$1
  Bottom 0.813: v182.88,17.78 R107.1
N$64
  Bottom 0.813: R107.2 183.53,23.19 R128.3
N$65  (via drill 1 pad 2.54)
  Top 0.813: v195.58,17.78 KEY30.P$1
  Bottom 0.813: v195.58,17.78 R106.1
N$66
  Bottom 0.813: R106.2 196.23,23.19 R127.3
N$67  (via drill 1 pad 2.54)
  Top 0.813: KEY11.P$1 v201.93,45.72
  Bottom 0.813: v201.93,45.72 R161.1
N$68
  Bottom 0.813: R161.2 201.28,40.31 R146.3
N$69  (via drill 1 pad 2.54)
  Top 0.813: v208.28,17.78 KEY31.P$1
  Bottom 0.813: v208.28,17.78 R105.1
N$70
  Bottom 0.813: R105.2 208.93,23.19 R126.3
N$71  (via drill 1 pad 2.54)
  Top 0.813: v214.63,45.72 KEY12.P$1
  Bottom 0.813: R160.1 v214.63,45.72
N$72
  Bottom 0.813: R160.2 213.98,40.31 R145.3
N$73  (via drill 1 pad 2.54)
  Top 0.813: v220.98,17.78 KEY32.P$1
  Bottom 0.813: v220.98,17.78 R104.1
N$74
  Bottom 0.813: R104.2 221.63,23.19 R125.3
N$75  (via drill 1 pad 2.54)
  Top 0.813: v233.68,17.78 KEY33.P$1
  Bottom 0.813: R103.1 v233.68,17.78
N$76
  Bottom 0.813: R103.2 234.33,23.19 R124.3
N$77  (via drill 1 pad 2.54)
  Top 0.813: KEY13.P$1 v240.03,45.72
  Bottom 0.813: v240.03,45.72 R159.1
N$78
  Bottom 0.813: R159.2 239.38,40.31 R144.3
N$79  (via drill 1 pad 2.54)
  Top 0.813: v246.38,17.78 KEY34.P$1
  Bottom 0.813: v246.38,17.78 R102.1
N$80
  Bottom 0.813: R102.2 247.03,23.19 R123.3
N$81  (via drill 1 pad 2.54)
  Top 0.813: KEY14.P$1 v252.73,45.72
  Bottom 0.813: v252.73,45.72 R158.1
N$82
  Bottom 0.813: R158.2 252.08,40.31 R143.3
N$83  (via drill 1 pad 2.54)
  Top 0.813: v259.08,17.78 KEY35.P$1
  Bottom 0.813: v259.08,17.78 R101.1
N$84
  Bottom 0.813: R101.2 259.73,23.19 R122.3
N$85  (via drill 1 pad 2.54)
  Top 0.813: KEY15.P$1 v265.43,45.72
  Bottom 0.813: v265.43,45.72 R157.1
N$86
  Bottom 0.813: R157.2 264.78,40.31 R142.3
N$87  (via drill 1 pad 2.54)
  Top 0.813: v271.78,17.78 KEY36.P$1
  Bottom 0.813: v271.78,17.78 R100.1
N$88
  Bottom 0.813: R100.2 272.43,23.19 R121.3
N$89
  Bottom 0.813: R10.1 LED4.K
N$90
  Bottom 0.813: R1.1 127,101.6 129.54,104.14 129.54,107.95 T4.3

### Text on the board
Top: 555 Contest - Synth V 0.2 | http://www.frank-buss.de/555/index.html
